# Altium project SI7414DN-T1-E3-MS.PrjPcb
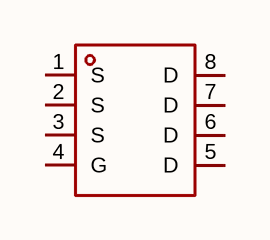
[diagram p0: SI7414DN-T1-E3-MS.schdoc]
1 sheet, 1 parts. Net scope: global (net labels, ports and power ports of the same name join across sheets).

## Sheet SI7414DN-T1-E3-MS.schdoc
size 127 x 101 mm

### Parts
Q?  si7414dn-t1-e3-ms  [POWERPAK-1212-8_L3.0-W3.0-P0.65-LS3.3-BL]  (value not drawn)

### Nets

Not connected (* = marked no-connect by the designer): Q? 1(S) 2(S) 3(S) 4(G) 5(D) 6(D) 7(D) 8(D)

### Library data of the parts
Q? = si7414dn-t1-e3-ms: 数量:1个N沟道;漏源电压(Vdss):60V;连续漏极电流(Id):20A;导通电阻(RDS(on)):24mΩ@10V;耗散功率(Pd):33W;阈值电压(Vgs(th)):1.8V;; Manufacturer: MSKSEMI(美森科); AddInBom: yes; ModelId: 74fc8db97a8d4d328d7f3b4acba39a5e; ModelTransform: 129.921,129.921,0,0,0,0,0,0,0; Number: 1个N沟道; Drain to Source Voltage: 60V; Current - Continuous Drain(Id): 20A; Pd - Power Dissipation: 33W; Gate Threshold Voltage (Vgs(th)): 1.8V; Gate Charge(Qg): 26nC; Input Capacitance(Ciss): 1.06nF; Reverse Transfer Capacitance (Crss@Vds): 54pF; Type: N沟道; Output Capacitance(Coss): 64pF; Vgs: ±20V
